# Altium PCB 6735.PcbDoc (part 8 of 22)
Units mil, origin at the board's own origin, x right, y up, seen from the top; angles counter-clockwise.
Board outline 2641.73 x 5165.35 mil, 6 copper layers (Top, Inner Layer 2, Inner Layer 3, Inner Layer 4, Inner Layer 5, Bottom), stack 35.7 mil thick; 1011 components, 790 nets, 4118 pads, 9325 vias.
Unrouted connection lines stored in the file: 4610.
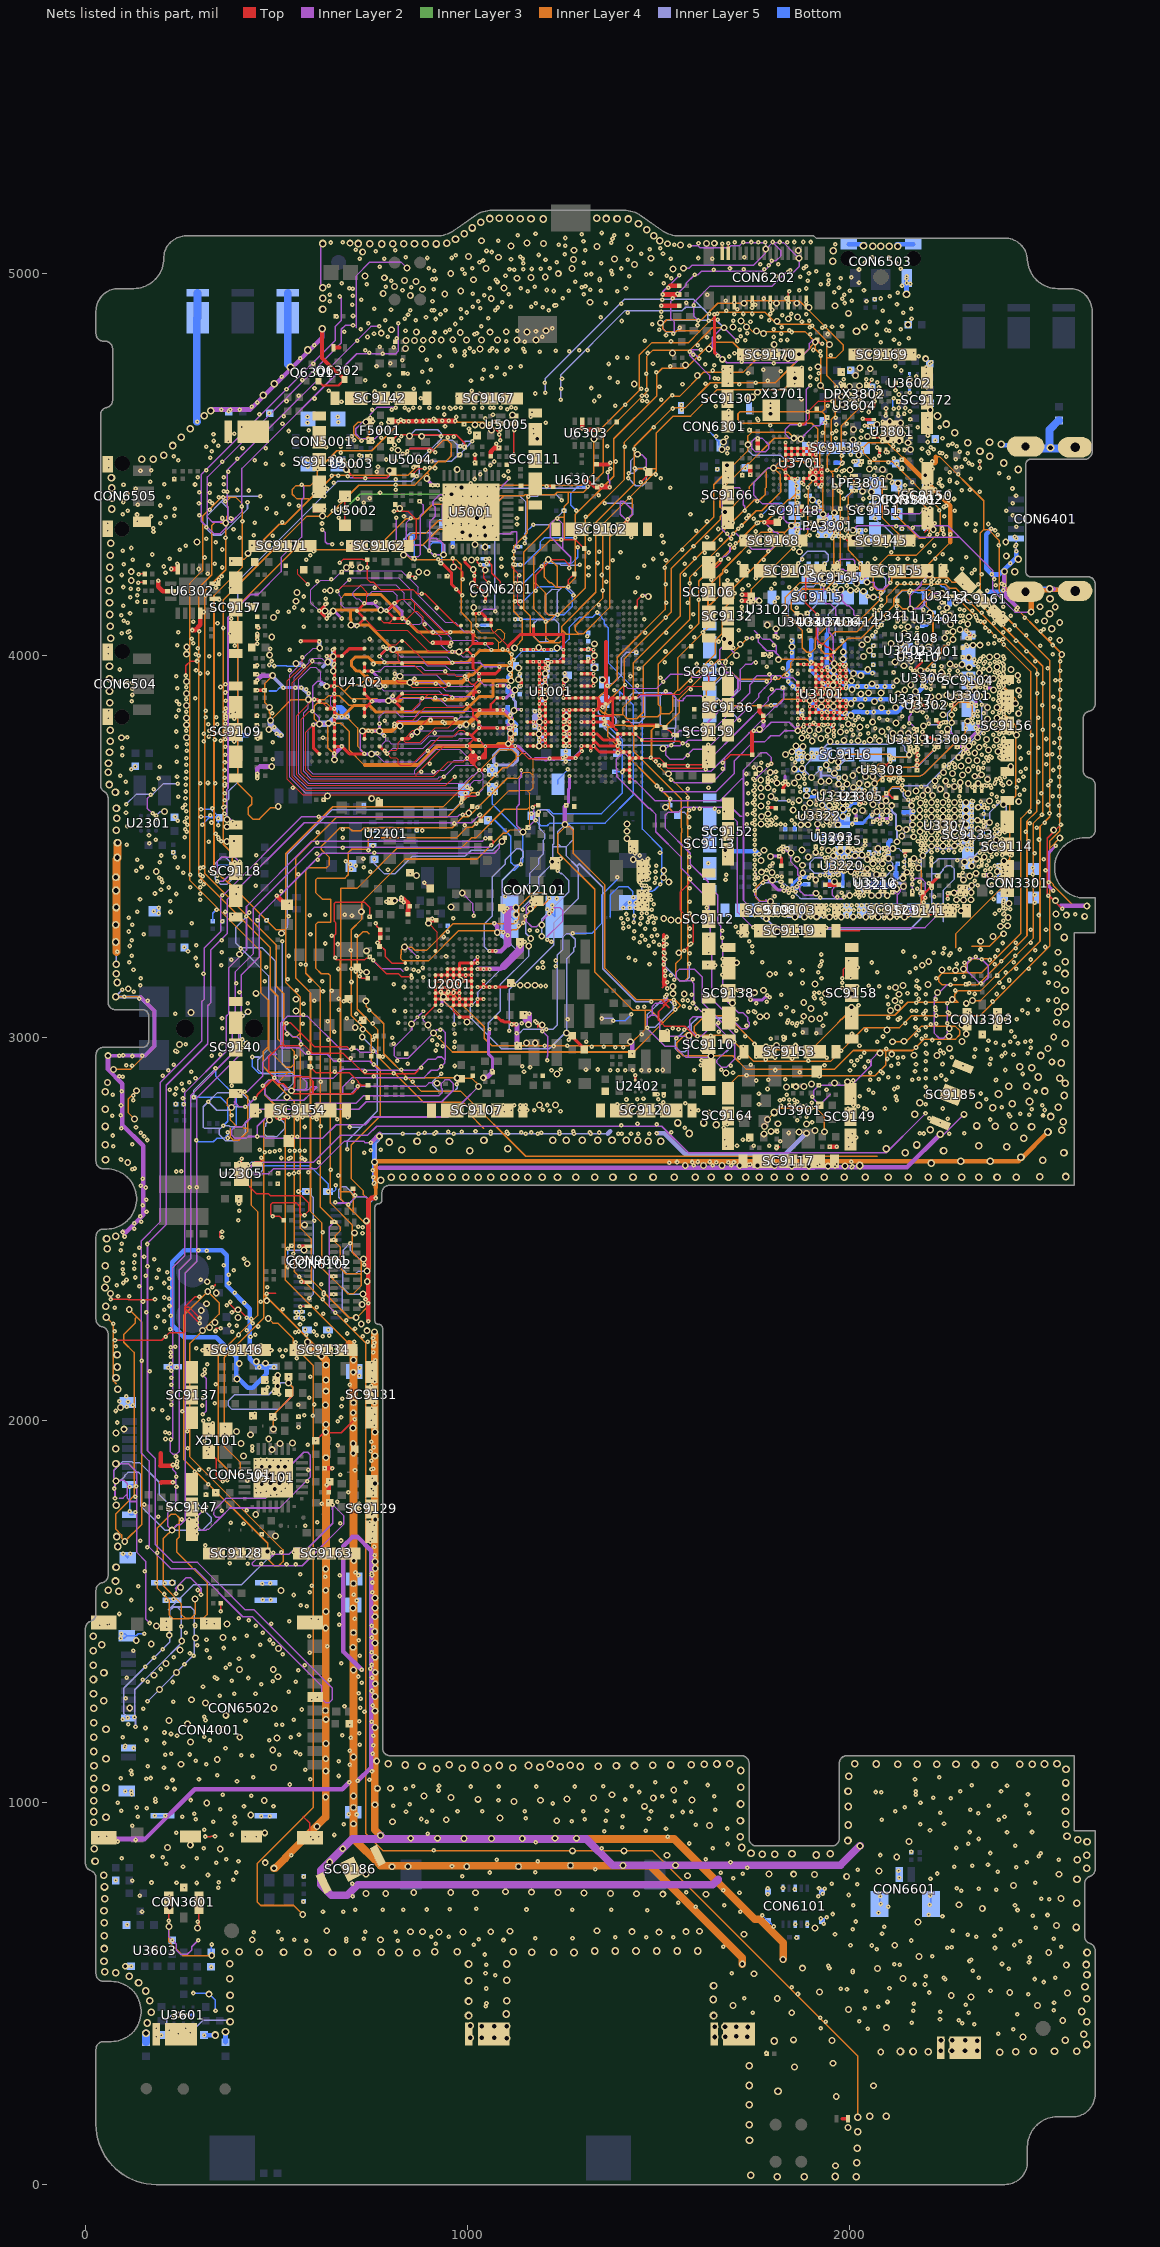
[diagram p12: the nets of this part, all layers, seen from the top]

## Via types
v1: diameter 12, hole 4, Top to Inner Layer 2, 3329 vias
v2: diameter 12, hole 4, Inner Layer 5 to Bottom, 3071 vias
v3: diameter 18, hole 10, Inner Layer 2 to Inner Layer 5, 1928 vias
v4: diameter 10, hole 4, Top to Inner Layer 2, 525 vias
v5: diameter 20, hole 12, Top to Bottom, 472 vias

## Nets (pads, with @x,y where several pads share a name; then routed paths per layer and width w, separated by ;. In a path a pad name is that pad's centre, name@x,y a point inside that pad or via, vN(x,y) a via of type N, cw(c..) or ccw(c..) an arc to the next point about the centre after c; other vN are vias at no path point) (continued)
D_GND: (continued)
  Inner Layer 2 w3: v3(583.08,3885.11) 583.08,3863.03 570.58,3850.53 570.58,3697.87 589.84,3678.61 921.29,3678.61 925.92,3683.23 v1(937.75,3683.23) 943.07,3688.56 944.07,3688.56 968.34,3712.83 1017.91,3712.83 v4(1029.98,3700.77) ; v1(593.83,3986.11) 598.33,3981.61 v3@629.08,3981.61 ; v1(596.08,3819.11) 582.58,3805.61 582.58,3702.84 594.82,3690.61 862.05,3690.61 ; v1(611.81,4117.11) 590,4138.92 590,4172.54 614.95,4197.49 647.13,4197.49 v1@671.92,4222.28 ; v3(613.08,4020.11) 595.34,4020.11 v1@571.39,3996.15 ; 616.08,3933.11 616.08,3956.11 602.58,3969.61 589.33,3969.61 558.58,3938.86 558.58,3691.36 583.33,3666.61 991.33,3666.61 1012.33,3687.61 1016.82,3687.61 v4(1029.98,3700.77) ; v1(651.18,3743.1) v3(651.27,3727.69) ; v1(651.18,3861.21) 642.34,3870.05 642.34,3891.74 v1(651.18,3900.58) ; v1(670.07,4219.89) v1@671.92,4222.28 ; v3(748.08,3743.11) 759.08,3743.11 780.08,3722.11 866.08,3722.11 910.85,3766.88 995.36,3766.88 v4(998.48,3763.76) ; v1(749.61,3959.63) 769.61,3959.63 782.58,3972.61 877.33,3972.61 887.83,3962.11 935.83,3962.11 947.83,3950.11 989.83,3950.11 998.08,3941.86 998.08,3937.38 v4(998.48,3936.99) ; v3(769.08,3803.11) 785.08,3787.11 785.08,3777.11 ; v3(769.08,3920.11) 769.29,3919.89 781.08,3908.11 923.83,3908.11 935.83,3896.11 959.83,3896.11 959.83,3890.49 v1(959.95,3890.49) ; v1(769.29,3821.84) 769.29,3840.11 783.08,3853.89 811.54,3853.89 823.33,3842.11 862.33,3842.11 874.83,3854.61 1029.58,3854.61 1031.08,3856.11 v4@1033.08,3856.11 ; v1(769.29,3999) 783.69,3984.61 883.33,3984.61 893.83,3974.11 941.83,3974.11 953.83,3962.11 1000.87,3962.11 1000.99,3962.23 1020.48,3962.23 v4(1029.98,3952.73) ; v1@788.59,3743.1 776.08,3755.61 776.08,3768.11 785.08,3777.11 ; v1@791.99,3746.11 803.99,3758.11 884.08,3758.11 905.08,3779.11 974.83,3779.11 979.33,3783.61 1025.87,3783.61 v4(1029.98,3779.51) ; v3@793.58,3882.11 800.58,3889.11 v1@876.08,3889.11 ; v3(805.08,4016.11) 824.58,3996.61 944.83,3996.61 960.02,3981.8 v1@960.21,3981.61 ; v1(808.66,4136.8) 816.15,4144.29 816.15,4156.32 804.2,4168.28 750.3,4168.28 736.06,4154.04 736.06,4142.93 v1(729.92,4136.8) ; v1@808.81,3880.75 835.45,3854.11 856.58,3854.11 876.08,3873.61 v1@876.08,3889.11 ; v1@808.92,3939.95 v3@819.08,3950.11 ; v1@809.51,3822.68 815.43,3828.61 866.83,3828.61 879.58,3841.36 960.58,3841.36 968.6,3833.34 v1(968.71,3833.45) 968.83,3833.11 974.83,3833.11 982.33,3840.61 1016.12,3840.61 1029.98,3826.74 ; v3(823.08,3946.11) v3@819.08,3950.11 ; v1(828.35,4097.43) 844.05,4081.72 874.93,4081.72 881.08,4087.88 881.08,4096.57 ; v3(849.08,3930.11) 849.58,3930.61 919.58,3930.61 942.08,3908.11 1027.36,3908.11 v4(1029.98,3905.48) ; v3(867.08,3800.11) 870.08,3803.11 962.83,3803.11 973.46,3813.73 989.71,3813.73 v3(996.08,3820.11) ; v3(977.08,4010.11) v3@977.08,4006.11 ; v4(998.48,3873.99) 992.98,3868.49 945.45,3868.49 924.83,3889.11 v1@876.08,3889.11 ; v4@1001.65,3729.09 1004.13,3726.61 989.41,3726.61 ; v1@1008.58,3653.83 1008.58,3665.11 1008.21,3665.48 ; v4(1014.23,3999.98) 1010.86,3996.61 986.58,3996.61 v3@977.08,4006.11 ; v4(1014.23,4062.97) 990.97,4062.96 966.89,4087.05 941.52,4087.05 870.15,4158.41 870.15,4178.71 826.59,4222.28 v1@671.92,4222.28 ; v4(1029.98,3811) 1029.58,3810.6 1014.59,3795.61 973.33,3795.61 968.83,3791.11 899.08,3791.11 878.08,3770.11 800.08,3770.11 793.08,3777.11 785.08,3777.11 ; v4(1029.98,3779.51) 1029.98,3779.21 v4(1046.08,3763.11) ; 1035.08,3855.11 v4@1034.08,3856.11 ; v4@1061.59,4015.61 v4(1045.72,4031.47) 1045.73,4032.23 1029.96,4032.23 1022.08,4040.11 962.83,4040.11 v1(956.83,4034.11) 956.83,4046.28 852.15,4150.96 852.15,4171.23 819.11,4204.28 694.25,4204.28 v1(658.33,4168.36) 663.58,4168.36 663.58,4157.86 668.08,4153.36 670.95,4153.36 669.1,4151.5 669.1,4133.79 677,4125.88 719,4125.88 v1(729.92,4136.8) ; v4@1077.22,3921.24 1074.12,3924.33 1042.01,3924.33 1036.06,3930.28 1036.06,3930.9 v4(1029.98,3936.99) 1013.1,3920.11 947.83,3920.11 917.83,3950.11 v3@819.08,3950.11 ; 1145.29,3750.49 1148.88,3750.49 1168.86,3730.51 1177.33,3730.51 ; v4(1392.18,3763.76) 1392.18,3778.6 1412.4,3798.83 1429.44,3798.83 1430.44,3797.83 1435.56,3797.83 1448.87,3784.52 1533.75,3784.52 v1@1539.31,3790.09 ; v4(1411.9,3923.47) 1411.9,3921.5 1418.31,3915.09 1494.31,3915.09 v1(1511.31,3932.09) ; v1(1750.72,3384.72) 1750.72,3372.95 1765.58,3358.09 1778.69,3358.09 1779.76,3357.02 v3(1791.99,3357.02) ; v1@571.39,3996.15 573.51,3994.03 570.96,3991.48 554.96,3975.48 554.31,3974.83 554.31,3969.6 534.58,3949.87 534.58,3681.42 574.91,3641.09 988.31,3641.09 995.31,3634.09 1022.41,3634.09 1040.58,3652.26 1040.58,3679.36 ; v1@571.39,3996.15 v1(566.95,3995.49) 566.73,3991.5 568.84,3993.6 v1@571.39,3996.15 ; v3@629.08,3981.61 631.5,3982.33 631.82,3982.43 v3(634.08,3983.11) 635.58,3981.61 v3@629.08,3981.61 ; v3@629.08,3981.61 629.08,3982.85 618.32,3993.61 590.72,3993.61 588.52,3991.41 585.41,3988.29 585.41,3982.66 546.58,3943.83 546.58,3686.39 578.36,3654.61 997.33,3654.61 1008.21,3665.48 ; v1(729.92,4136.8) 727.07,4136.8 714.55,4149.32 708.92,4149.32 699.53,4158.71 699.53,4161.9 700.97,4163.34 700.97,4166.16 721.08,4186.28 811.65,4186.28 834.15,4163.78 834.15,4143.5 881.08,4096.57 ; 862.05,3690.61 862.05,3700.59 916.13,3754.67 978.78,3754.67 998.48,3734.97 v4(998.48,3732.26) 995.06,3732.26 989.41,3726.61 ; 862.05,3690.61 912,3690.61 921.98,3700.59 938.82,3700.59 964.84,3726.61 989.41,3726.61 ; 881.08,4096.57 891.48,4086.17 912.8,4064.85 931.23,4046.42 931.23,4027.89 950.51,4008.61 974.58,4008.61 v3@977.08,4006.11 ; 1008.21,3665.48 1016.83,3674.11 1023.89,3674.11 ; 1023.89,3674.11 1035.33,3674.11 ; 1023.89,3674.11 1024.48,3673.52 1034.74,3673.52 1035.33,3674.11 ; v4(1029.98,3700.77) 1040.58,3690.16 1040.58,3679.36 ; v4@1033.08,3856.11 v4(1031.08,3858.11) 1032.08,3858.11 v4@1034.08,3856.11 ; v4@1033.08,3856.11 v4@1034.08,3856.11 ; 1035.33,3674.11 1040.58,3679.36
  Inner Layer 2 w4: v3(65.31,2330.92) 65.59,2331.2 65.95,2330.83 v1(65.95,2315.83) ; v1(77.31,1796.09) 77.31,1838.09 v3(80.31,1841.09) ; 88.31,1796.09 98.53,1796.09 109.31,1806.87 ; v1(168.31,1469.09) 157.31,1480.09 157.31,1630.98 134.51,1653.78 134.51,1787.09 ; v1(171.28,3635.71) 161.31,3625.74 161.31,3601.09 175.07,3587.33 v1(176.03,3587.33) ; v1(218.31,690.09) 218.31,678.09 217.31,677.09 217.31,675.09 v3(218.31,675.09) 218.31,648.26 237.31,629.26 237.31,613.82 249.03,602.11 265.62,602.11 265.78,602.26 266.41,602.26 278.12,613.98 278.12,621.91 v1(295.3,639.09) ; v1(229.06,1882.65) 228.31,1879.43 228.31,1871.09 236.51,1862.89 236.51,1851.77 236.51,1778.75 215.31,1757.55 215.31,1723.09 v3(226.31,1712.09) 240.31,1726.09 248.8,1726.09 261.31,1738.6 261.31,2384.98 291.31,2414.98 291.31,2842.72 401.31,2952.72 401.31,3037.29 407.31,3043.29 407.31,3164.54 455.31,3212.54 455.31,3321.35 456.31,3322.35 456.31,3322.44 497.02,3363.15 497.12,3363.15 501.75,3367.78 504.12,3367.78 619.42,3483.09 1069.36,3483.09 1082.31,3496.04 1082.31,3504.83 1090.35,3512.87 v3(1089.69,3513.53) v3@1090.39,3516.8 ; 235.31,1560.09 236.95,1561.72 ; v1(236.95,1545.49) 236.95,1561.72 ; v1(302.31,1543.09) 302.31,1560.06 275.29,1587.09 262.31,1587.09 242.85,1567.62 236.95,1561.72 ; v1(307.31,1763.09) 295.31,1751.09 295.31,1719.12 302.34,1712.09 315.1,1712.09 317.1,1714.09 322.11,1714.09 354.11,1746.09 ; v1(307.31,2015.09) 316.31,2024.09 316.31,2109.09 v1(307.31,2118.09) ; v1(344.27,3424.72) 344.27,3461.36 355.77,3472.87 391.5,3472.87 v1(403.36,3461) ; v1(344.95,3409.83) 360.53,3409.83 390.31,3439.62 v1(390.31,3460.09) ; v1(354.76,3514.14) 369.83,3514.14 v3(369.83,3513.77) ; v1@372.95,4486.49 v1@370.98,4484.51 ; v3(381.73,2818.12) 391.17,2827.55 394.31,2827.55 ; 389.31,2832.55 392.18,2829.68 ; v1(394.5,3556.6) 374.63,3576.47 369.31,3581.79 369.31,3649.04 372.95,3652.68 372.95,3801.78 372.95,3903.37 372.95,4100.69 432.36,4160.09 452,4160.09 511.95,4220.04 511.95,4256.92 565.31,4310.28 565.31,4407.91 571.07,4413.67 571.07,4442.07 v1(565.41,4447.73) ; v1(404.79,2855.36) 392.18,2842.76 392.18,2829.68 ; v1@421.18,2858.09 464.31,2901.22 464.31,2936.63 484.77,2957.09 500.99,2957.09 ; v1(443.11,2842.42) 420.79,2820.09 401.78,2820.09 394.31,2827.55 ; v1(525.95,3038.57) 522.31,3038.57 522.31,3022.26 531.95,3012.62 540.74,3003.83 541.48,3003.09 553.28,3003.09 563.95,2992.42 v1(563.95,2983.83) ; v3(612.08,3821.11) v3@612.08,3822.11 ; v1(619.95,4329.83) 627.6,4322.18 627.6,4298.38 632.89,4293.09 644.69,4293.09 v1(645.95,4291.83) ; v5(620.65,4963.09) 615.65,4968.09 615.65,5072.71 v5(621.25,5078.31) ; v1(621.69,3623.09) 621.97,3622.81 632.6,3633.44 v3(632.88,3633.16) ; v3(636.08,3823.11) 636.08,3822.11 v3@612.08,3822.11 ; v1(650.95,2518.49) 637.3,2504.84 637.3,2297.1 v1(653.31,2281.09) ; v1(651.18,3920.26) 631.5,3920.26 618.65,3933.11 616.08,3933.11 607.08,3933.11 594.08,3920.11 594.08,3885.37 594.08,3855.36 612.08,3837.36 v3@612.08,3822.11 ; v1(653.3,2570.09) 655.3,2568.09 691.1,2568.09 707.1,2584.09 734.31,2584.09 739.31,2579.09 759.31,2579.09 v1(759.31,2581.09) ; v1(661.95,4382.49) v3(677.48,4382.29) ; v1(664.95,4939.83) 668.95,4935.83 668.95,4876.73 652.95,4860.73 652.95,4824.3 302.95,4474.3 302.95,4351.83 335.95,4318.83 352.31,4318.83 369.31,4335.83 v3@369.31,4345.09 ; v1(685.74,4469.48) 688.93,4469.48 693.31,4465.09 789.31,4465.09 796.39,4472.17 796.39,4479.34 v3(795.34,4484.55) ; v1(699.95,4864.83) 680.01,4864.83 669.31,4854.14 669.31,4818.01 318.95,4467.65 318.95,4404.38 318.95,4362.83 331.95,4349.83 369.31,4349.83 v3@369.31,4345.09 ; 708.95,4857.65 708.95,4994.69 744.09,5029.83 825.57,5029.83 v3(841.31,5014.09) ; v3(725.08,3803.11) 718.95,3796.98 718.95,3754.07 v1(729.92,3743.1) ; v3(733.91,4611.3) 724.91,4611.3 716.69,4603.09 707.31,4593.72 707.31,4580.46 719.68,4568.09 758.31,4568.09 773.95,4583.73 v1(773.95,4606.49) ; v1(743.79,3211.76) 774.46,3181.09 824.31,3181.09 831.31,3174.09 ; v1(745.11,4622.95) 745.11,4631.09 760.31,4646.83 763.57,4650.09 807.69,4650.09 810.71,4647.07 v1(812.33,4648.69) ; v1(746.95,2725.83) 732.08,2725.83 728.82,2729.09 676.71,2729.09 604.71,2657.09 491.06,2657.09 479.06,2645.09 442.33,2645.09 433.31,2654.11 433.31,2666.07 442.33,2675.09 597.03,2675.09 667.03,2745.09 737.88,2745.09 761.88,2769.09 1508.05,2769.09 1577.58,2699.56 2095.02,2699.56 2183.55,2788.09 v1(2197.95,2802.49) ; v1(768.95,4861.49) 746.81,4861.49 370.41,4485.08 v1@370.98,4484.51 ; v3@769.29,3919.89 v3@769.29,3921.11 ; v1(778.31,2951.09) 769.04,2951.09 757.04,2963.09 717.99,2963.09 710.99,2970.09 v1(695.95,2970.09) 667.11,2970.09 581.11,3056.09 528,3056.09 511.31,3039.4 511.31,2975.41 515.31,2971.41 518.73,2974.83 557.9,2974.83 575.77,2956.96 632.43,2956.96 650.43,2938.96 694.04,2938.96 694.17,2939.09 743.97,2939.09 766.95,2916.11 766.95,2915.09 ; v1@788.59,3743.1 v1(788.98,3743.1) ; v3@803.08,4018.11 803.08,4018.69 v3(805.08,4016.11) ; v1(808.66,3821.84) v1@809.51,3822.68 ; v1(808.66,3939.95) v1@808.92,3939.95 ; v3(809.31,3359.09) 809.31,3359.59 826.31,3359.59 v1(826.31,3360.09) ; v1(812.71,4360.88) 812.71,4294.49 838.22,4268.99 848.72,4258.49 869.95,4258.49 876.31,4264.85 876.31,4289.85 ; v1(817.95,4869.49) 817.95,4796.49 811.55,4790.09 709.53,4790.09 409.31,4489.87 409.31,4377.09 381.31,4349.09 375.52,4349.09 v3@374.15,4347.72 ; v3(834.79,3238.14) 834.79,3237.29 842.89,3237.29 868.41,3211.77 869.07,3211.11 v4@868.95,3210.99 ; v1(841.89,4535.07) 848.91,4542.09 905.31,4542.09 v1(915.31,4532.09) ; v1(850.95,4359.49) 838.95,4347.49 838.95,4304.96 854.43,4289.49 875.95,4289.49 876.31,4289.85 ; v1(873.95,4403.98) 883.31,4394.61 883.31,4374.55 876.31,4367.55 876.31,4289.85 ; v3(879.64,4574.27) 882.79,4577.42 926.53,4577.42 v1(930.27,4573.68) ; v4(884.09,3054.22) 884.08,3045.56 v3(896.26,3033.38) ; v4(884.09,3069.96) v4(868.34,3054.22) 869.1,3053.45 852.52,3036.87 v3(853.29,3036.1) 853.29,3020.94 807.31,2974.97 807.31,2954.12 814.34,2947.09 844.31,2947.09 v3(910.31,3013.09) 918.09,3020.87 934.53,3020.87 940.98,3014.42 940.98,2942.73 940.31,2942.06 ; v3(919.7,2881.33) v3@924.31,2882.09 ; v1(939.3,4421.28) 926.54,4421.28 909.31,4404.06 909.31,4394.11 915.31,4388.11 915.31,4365.1 900.31,4350.1 900.31,4306.09 ; v3(957.29,4422.28) 957.29,4417.21 955.59,4417.21 932.95,4394.58 932.95,4348.49 966.95,4314.49 v1(966.95,4305.49) ; v1(959.83,3981.61) 960.21,3981.61 1033.17,3981.61 1044.29,3970.49 v4(1082.95,3970.49) ; v1(959.95,3890.49) 961.55,3892.09 1014.23,3892.09 v4(1014.23,3889.74) ; v3(985.95,3378.83) 1012.95,3351.83 1012.95,3333.24 1016.31,3329.88 v1(1016.31,3319.24) ; v1(987.42,3583.34) 978.21,3583.34 973.96,3579.09 565.79,3579.09 354.3,3367.6 354.3,3279.15 311.31,3236.16 311.31,3101.85 303.96,3094.49 303.96,2991.44 195.31,2882.8 195.31,2518.4 146.31,2469.4 146.31,1913.29 166.51,1893.09 166.51,1668.11 223.17,1611.45 285.84,1611.45 411.65,1485.65 436.72,1485.65 617.63,1304.73 617.63,1271.8 628.34,1261.09 638.28,1261.09 645.31,1268.12 645.31,1299.68 441.11,1503.88 417.22,1503.88 293.4,1627.71 229.54,1627.71 182.51,1674.74 182.51,1899.9 162.31,1920.1 162.31,2462.58 211.31,2511.58 211.31,2876.11 320.11,2984.91 320.11,3084.39 327.31,3091.6 327.31,3229.49 370.63,3272.81 370.63,3361.3 572.42,3563.09 1010.89,3563.09 1025.45,3577.65 1026.34,3577.65 v1(1032.3,3583.61) ; v4(992.95,3180.49) 1003.27,3180.49 1016.14,3193.36 1016.14,3202.02 v4(1025.82,3211.7) ; v3(997.95,3041.83) 997.95,3042.1 v4(1010.07,3054.22) ; v4(998.48,3732.26) 1001.65,3729.09 1026.8,3729.09 v4(1029.98,3732.26) ; v3(1028.62,2872.67) v3@1028.6,2872.86 ; v4@1029.58,3810.6 v4(1029.98,3811) ; v4(1029.98,3700.77) v4(1045.72,3700.77) ; v4(1029.98,4110.21) 1041.86,4122.09 1075.31,4122.09 ; v1(1046.62,3522.84) 1038.87,3515.09 592.3,3515.09 421.31,3344.1 421.31,3229.94 375.31,3183.94 375.31,3063.71 368.31,3056.71 368.31,2964.98 259.31,2855.98 259.31,2430.24 228.31,2399.24 228.31,2191.16 228.31,2128.99 228.31,2040.13 228.31,1950.52 221.31,1943.52 221.31,1918.12 228.34,1911.09 238.28,1911.09 245.31,1918.12 245.31,2392.52 275.31,2422.52 275.31,2849.35 384.31,2958.35 384.31,3046.66 391.31,3053.66 391.31,3172.54 439.31,3220.54 439.31,3339.47 598.93,3499.09 1054.98,3499.09 1060.97,3505.08 v1(1062.02,3504.03) ; v1(1106.95,4464.49) 1106.95,4460.09 1071.31,4424.45 1071.31,4327.87 1080.1,4319.09 1111.31,4319.09 1116.71,4324.49 1128.95,4324.49 1128.95,4281.49 v1(1120.95,4273.49) ; v4(1140.21,3700.77) 1140.21,3682.49 1134.95,3677.23 1134.95,3611.07 1128.95,3605.07 1128.95,3555.09 1139.95,3544.09 1150.69,3544.09 1173.3,3566.7 1173.3,3600.14 v1@1170.95,3602.49 ; v1(1166.95,3356.83) 1152.95,3342.83 1152.95,3305.62 1167.74,3290.83 1180.17,3290.83 1197.95,3308.62 1197.95,3310.28 v1@1213.16,3325.49 ; v1(1171.51,4593.7) 1171.31,4593.7 1171.31,4578.37 v3(1182,4567.68) ; v1(1194.95,3017.83) 1209.39,3003.39 1209.39,2952.85 1208.28,2951.74 v1(1208.28,2941.03) ; 1206.95,3263.83 1249.14,3306.02 1249.14,3333.61 1241.92,3340.83 1226.76,3340.83 v1(1220.95,3335.02) ; 1207.31,4437.09 v1(1207.31,4443.09) ; v4(1218.95,3984.23) 1234.51,3984.23 1239.25,3988.97 1245.7,3995.41 ; 1245.7,3995.42 1250.45,4000.17 v4@1250.45,4015.72 ; v1(1265.89,4229.49) 1265.89,4239.35 1269.89,4243.35 1269.89,4257.65 1247.45,4280.09 ; v1(1371.31,4441.23) 1371.31,4457.22 1367.31,4461.22 1367.31,4482.65 1373.41,4488.74 v1(1372.72,4489.43) ; v4@1423.68,3889.74 1446.75,3889.74 1452.1,3895.09 1504.63,3895.09 1511.63,3902.09 1531.27,3902.09 1551.53,3881.83 1563.95,3881.83 1563.95,3886.04 1572.74,3894.83 1610.64,3894.83 1617.88,3887.6 1625.13,3887.6 1629.23,3883.49 1638.71,3883.49 1641.11,3881.09 1662.72,3881.09 1667.5,3885.88 1685.62,3885.88 1694.41,3894.66 1694.41,3901.07 1696.21,3902.87 1696.21,3903.51 1707.31,3914.61 1707.31,3938.75 1690.17,3955.89 1677.74,3955.89 1674.77,3952.92 ; v3(1444.2,4526.99) 1444.2,4526.09 1455.2,4526.09 1467.43,4513.86 1467.43,4490.09 v1(1464.31,4489.09) ; v1(1457.52,4156.53) 1458.31,4159.09 1468.31,4159.09 v3(1472.66,4154.69) ; v1(1495.31,3659.09) 1502.16,3652.25 1502.16,3650.93 1504.51,3648.58 1509,3644.09 1649.71,3644.09 1697.65,3692.03 1697.65,3724.69 1748.14,3775.17 1761.15,3775.17 1761.21,3775.24 1777.67,3775.24 1793.06,3790.63 1816.1,3790.63 1829.07,3803.59 v3(1863.65,3803.59) 1841.49,3825.75 1794,3825.75 1769.76,3801.51 1767.74,3799.49 1738.51,3799.49 1736.48,3797.45 ; v1(1510.31,4945.09) 1510.31,4952.09 v1(1553.31,4995.09) ; v1(1511.31,3932.09) 1530.31,3951.09 1581.58,3951.09 1589.51,3943.16 1599.34,3943.16 1599.97,3943.79 1608.43,3943.79 1616.23,3951.59 1673.44,3951.59 1674.77,3952.92 ; v1(1521.31,3113.09) 1521.31,3101.71 1519.32,3099.71 1510.69,3091.09 1491.71,3091.09 1483.31,3082.69 1483.31,3059.09 ; v3(1525.31,3691.09) 1532.35,3698.13 1637.15,3698.13 1672.29,3733.27 ; v1(1532.06,3675.97) 1539.94,3668.09 1639.67,3668.09 1672.29,3700.71 1672.29,3733.27 ; v1(1537.95,4841.83) 1540.95,4841.83 1540.95,4872.8 1530.95,4882.8 1530.95,4926.83 1537.95,4933.83 v1(1536.95,4934.83) 1538.45,4935.33 1549.45,4946.33 v1(1548.95,4946.83) 1571.45,4969.33 1571.45,4974.33 v1(1593.95,4996.83) 1602.73,4996.83 1611.18,5005.29 1774.72,5005.29 1787.95,5018.52 v1(1787.95,5021.83) 1799.39,5033.27 1806.63,5033.27 1819.45,5046.08 1819.45,5059.33 1797.95,5080.83 v1(1798.44,5082.36) ; v1(1538.31,3793.09) 1539.31,3790.09 1540.45,3790.09 1553.45,3803.09 1605.49,3803.09 1618.77,3816.37 1640.01,3837.61 1640.01,3837.68 1654.31,3851.98 1654.31,3852.46 1713.74,3911.9 1713.74,3964.07 1726.85,3977.17 1741.87,3977.17 1749.29,3984.59 1756.65,3984.59 1754.15,3982.09 v1(1754.01,3982.23) ; v3(1564.95,5013.83) 1578.95,5013.83 1586.95,5021.83 1747.95,5021.83 1778.95,5052.83 1778.95,5063.83 v3@1779.45,5063.83 ; v1(1580.31,5073.09) 1601.73,5073.09 1606.98,5067.83 1684.14,5067.83 1689.14,5072.83 1710.85,5072.83 1718.85,5080.83 1720.91,5080.83 v1(1720.91,5082.12) 1720.95,5080.83 1741.89,5080.83 v1(1741.89,5082.29) 1741.95,5080.83 v1@1759.94,5080.83 ; v1@1591.24,3151.44 v1(1589.27,3153.41) ; v1(1603.31,4877.09) 1591.31,4889.09 1591.31,4924.06 1634.34,4967.09 1796.71,4967.09 1829.71,5000.09 1849.29,5000.09 1866.95,5017.75 v3(1866.95,5039.83) 1855.06,5051.72 1855.06,5051.91 1826.14,5080.83 1817.05,5080.83 v1(1817.05,5082.31) 1816.95,5080.83 1798.44,5080.83 v1(1798.44,5082.36) ; v1(1605.95,4777.49) 1599.59,4783.85 1599.59,4784.25 1588.85,4794.99 v1(1580.85,4794.99) ; v1(1610.31,4800.09) 1594.69,4800.09 1594.13,4800.65 1586.5,4800.65 v1(1580.85,4794.99) ; v1(1624.31,3726.13) v1(1624.31,3726.13) 1630.32,3726.09 1712.01,3807.79 1712.01,3807.86 1785.95,3881.8 1785.95,3889.16 1785.95,3890.59 1800.62,3905.25 1800.62,3905.58 1807.65,3912.6 1817.59,3912.6 1817.75,3912.44 1824.77,3912.44 1826.65,3910.56 1826.65,3884.62 1820.17,3878.14 1809.29,3867.24 1805.33,3867.24 1736.01,3797.92 1736.48,3797.45 ; v1(1626.79,3311.09) v1@1630.79,3311.09 ; v1(1630.31,3264.09) v1@1634.95,3264.09 ; 1632.95,4723.38 1632.95,4733.4 1580.85,4785.5 v1(1580.85,4794.99) ; v3(1636.31,2953.09) 1632.31,2949.09 1577.31,2949.09 ; v1(1645.99,3599.84) 1648.72,3599.84 1651.31,3602.43 1651.31,3603.09 ; v1(1662.31,4251.39) 1670.67,4259.74 1674.49,4259.74 1686.31,4271.57 v1(1686.31,4290.09) ; v1(1666.59,3238.74) 1666.59,3259.49 1665.12,3260.96 1662.74,3263.34 1662.74,3292.1 1654.79,3300.05 1654.79,3373.09 1629.44,3398.45 1629.44,3408.5 1582.63,3455.3 1582.63,3482.96 1516.32,3549.27 1516.32,3550.69 1516.75,3551.12 1516.75,3569.12 1516.68,3569.19 1516.68,3581.61 1516.75,3581.68 1516.75,3582.44 1524.4,3590.09 1525.16,3590.09 1525.48,3590.41 1537.89,3590.41 1538.21,3590.09 1550.52,3590.09 1564.52,3604.09 1645.99,3604.09 1651.31,3604.09 ; 1667.41,3245.35 1667.41,3238.74 1667.41,3119.71 1669.44,3117.68 1669.44,3105.35 v3@1688.4,3086.39 ; v1(1690.08,4306.11) 1666.31,4329.88 1666.31,4425.79 1679.61,4439.09 1711.53,4439.09 1721.31,4429.3 1721.31,4394.76 1724.98,4391.09 v1(1724.98,4378.74) ; v3(1692.95,3091.6) 1692.95,3091.4 1693.18,3091.17 v3@1688.4,3086.39 ; 1703.31,4320.09 1703.31,4318.87 1743.1,4279.09 1794.53,4279.09 1817.31,4301.87 1817.31,4314.3 1808.53,4323.09 1802.31,4323.09 v1(1776.31,4349.09) ; v3(1703.65,4000.59) 1703.65,4001.08 1680.24,4024.49 1668.25,4024.49 1659.08,4015.32 1659.08,3983.39 v1(1674.77,3967.7) 1674.77,3952.92 ; v1(1705.31,4823.09) v3(1670.31,4858.09) 1665.31,4858.09 1639.31,4832.09 1639.31,4804.87 1677.66,4766.52 1856.97,4766.52 1864.93,4774.49 ; 1717.65,3580.17 1713.19,3580.17 1673.27,3620.09 1659.75,3620.09 ; v1@1725.65,4049.59 v1(1729.65,4045.59) 1729.65,4045.73 1745.04,4045.73 v1(1745.04,4045.88) ; 1737.93,3923.27 1737.93,3902.14 1678.31,3842.52 1678.31,3842.04 1664.01,3827.74 1664.01,3827.67 1615.43,3779.09 1577.33,3779.09 1570.31,3772.08 1562.31,3772.08 v1(1562.31,3771.09) 1555.84,3764.62 1526.21,3764.62 1518.77,3757.18 1518.77,3739.63 1529.77,3728.64 1562.5,3728.64 1588.69,3754.82 1625.11,3754.82 1688.01,3817.73 1688.01,3817.8 1702.31,3832.1 1702.31,3832.58 1761.95,3892.22 1761.95,3899.1 1761.95,3900.52 1776.62,3915.19 1776.62,3915.52 1793.43,3932.33 1793.43,3933.35 1793.76,3933.68 1793.76,3942.95 1791.07,3945.63 1791.07,3947.59 ; 1737.94,3923.28 1737.94,3923.52 1747.85,3933.43 1747.85,3938.25 1757.19,3947.59 1791.07,3947.59 ; v1(1738.65,3342.59) 1721.65,3359.59 1721.65,3678.38 ; 1749.65,4065.59 1771.65,4043.59 1790.34,4043.59 1807.65,4026.28 1807.65,4006.59 ; v1(1750.65,3414.59) 1753.65,3412.83 1753.65,3433.59 ; v1(1750.65,3674.59) 1774.11,3698.04 1775.11,3698.04 v1(1794.65,3717.59) 1794.65,3733.59 1782.65,3745.59 1766.65,3745.59 ; v1(1760.65,4050.59) 1760.65,4034.9 1782.72,4012.83 1801.41,4012.83 1807.65,4006.59 ; 1767.96,3745.35 1766.31,3745.35 1721.65,3700.7 1721.65,3678.38 ; 1780.02,3361.97 1780.65,3361.35 1780.65,3358.59 ; v3(1800.31,4491.09) 1786.1,4491.09 1748.31,4453.3 1748.31,4420.12 1760.83,4407.61 1771.35,4397.09 1784.8,4397.09 1785.8,4398.09 1812.29,4398.09 1826.31,4384.06 1826.31,4357.87 1836.1,4348.09 1839.31,4348.09 v3(1847.31,4340.09) 1855.91,4331.49 1910.87,4331.49 v3@1910.87,4336.09 ; v3(1813.65,3989.59) 1813.65,4000.59 1807.65,4006.59 ; v1(1837.65,3391.59) 1851.35,3391.59 1866.65,3406.89 1866.65,3421.64 1865.65,3422.64 1865.65,3423.6 1864.65,3424.6 1864.65,3425.5 1863.65,3426.5 1863.65,3442.39 1845.65,3460.39 v3(1845.65,3483.59) ; v3(1853.31,4569.09) 1842.31,4569.09 1830.31,4581.09 1830.31,4591.06 1843.34,4604.09 v1(1868.31,4604.09) 1884.31,4604.09 1886.31,4606.09 1886.31,4697.09 v1(1896.31,4707.09) ; v4(1863.66,3914.34) 1863.66,3921.51 1860.53,3924.64 1860.53,3933.03 1851.72,3941.83 1823.73,3941.83 1817.97,3947.59 1791.07,3947.59 ; 1865.95,4773.46 1864.93,4774.49 ; v3(1871.31,4567.09) 1882.2,4577.98 1882.2,4578.77 1904.52,4601.09 1920.53,4601.09 1934.49,4615.04 1934.49,4617.26 v1(1941.31,4624.09) ; v1(1875.42,4368.16) 1884.35,4377.09 1919.87,4377.09 v3@1928.09,4368.87 ; v3(1876.65,3431.59) 1868.65,3423.59 1868.65,3385.31 1880.37,3373.59 1903.65,3373.59 1908.65,3378.59 v3(1911.65,3378.59) ; v4(1879.41,3977.33) v4(1895.16,3977.33) ; v3(1906.31,4332.09) v3@1910.87,4336.09 ; v3(1909.3,4821.09) 1903.81,4826.58 1894.3,4817.07 1894.3,4803.86 1864.93,4774.49 ; v1(1914.67,4107.68) 1915.62,4107.68 1944.62,4078.68 1944.62,4062.5 1956.68,4050.44 1956.68,3986.9 1944.37,3974.59 1935.57,3974.59 1926.65,3965.68 v4(1926.65,3961.58) ; v3(1916.48,4085.83) 1916.48,4029.31 v1(1921.36,4024.43) ; v3@1928.09,4368.86 v3(1929.31,4370.09) ; v1(1931.65,4186.09) 1931.65,4168.95 1929.15,4166.45 1929.15,4158.3 1928.56,4157.71 1928.56,4145.29 1937.35,4136.5 1937.53,4136.5 1937.63,4136.4 1948.14,4136.4 1956.04,4128.5 1956.54,4128.5 1957.04,4128 1963.35,4121.69 1963.35,4105.71 1965.49,4103.56 1965.49,4086.89 v3(1970.49,4086.89) ; 1943.31,4373.09 1943.31,4368.53 v3@1910.87,4336.09 ; 1949.06,2852.56 v1(1921.08,2824.58) 1904.95,2840.71 1904.95,2861.75 v1(1919.46,2876.26) 1993.71,2876.26 2004.57,2876.26 2055.24,2926.93 2055.24,2942.32 2078.43,2965.5 2079.21,2964.73 v3(2079.21,2960.09) ; 1959.31,4236.09 1975.37,4252.15 2008.54,4252.15 ; v3(1959.68,3409.09) 1959.68,3396.52 1957.24,3394.08 1957.24,3391.13 1954.22,3388.11 1954.22,3386.2 1953.65,3385.63 1953.65,3373.55 1963.61,3363.59 1978.52,3363.59 1987.86,3372.92 v3(1999.69,3372.92) ; v1(1969.65,4226.59) 1982.76,4226.59 1987.7,4221.65 2005.31,4221.65 2012.81,4229.15 2012.81,4247.87 2008.6,4252.09 ; v3(1976.65,4173.59) 1976.65,4161.91 1981.06,4157.5 1981.06,4142.29 1992.85,4130.5 1997.71,4130.5 2010.06,4118.15 2010.06,4108 v3(2020.06,4098) ; v3(2007.77,4328.17) 2019.43,4339.83 2152.13,4339.83 2182.31,4309.65 2194.7,4309.65 2194.88,4309.83 2208.95,4309.83 ; v1(2030.65,4202.59) 2040.25,4202.59 2053.81,4216.15 2094.03,4216.15 2102.81,4207.36 2102.81,4188.94 2094.03,4180.15 2092.51,4180.15 2086.43,4174.07 ; v3(2044.81,4192.15) 2063.87,4192.15 2063.87,4182.77 2072.65,4173.98 2073.87,4173.98 2086.3,4173.97 2086.4,4174.07 ; v1(2094.33,4396.09) 2094.33,4383.83 2107.33,4370.83 2182.04,4370.83 v1(2193.3,4382.09) ; v3(2140.64,3395.82) 2132.16,3387.33 2132.16,3382.94 2123.65,3374.43 2123.65,3346.31 2135.37,3334.59 2173.65,3334.59 v1(2193.65,3354.59) ; v3(2155.25,3740.69) 2156.66,3740.69 2156.66,3756.08 v1(2158.08,3756.08) ; v1(2160.65,3855.59) 2160.65,3846.59 2154.46,3840.4 2154.46,3827.06 v1(2175.34,3806.18) ; v1(2163.81,3381.58) 2163.81,3391.42 2162.65,3392.59 2162.65,3407.63 2172.61,3417.59 2186.69,3417.59 2197.6,3406.69 v1(2197.6,3366.48) ; v1(2164.95,4334.83) 2169.95,4339.83 2256.52,4339.83 2286.52,4309.83 ; v3(2208.31,4213.15) 2186.81,4191.65 2186.81,4185.86 2158.31,4157.36 2158.31,4126.25 v3@2155.68,4123.62 ; v1(2208.95,4316.83) 2208.95,4309.83 ; v1(2230.65,3322.59) 2196.62,3288.56 1895.47,3288.56 1894.94,3289.09 1801.76,3289.09 1801.44,3288.77 1746.19,3288.77 1705.65,3329.31 1705.65,3564.95 1667.51,3603.09 1651.31,3603.09 ; v3(2241.06,4163.5) 2240.81,4163.65 2220.81,4163.65 2180.78,4123.62 v3@2155.68,4123.62 ; 2246.04,2747.83 v3(2298.3,2800.09) ; v1(2254.84,3090.66) 2254.84,3009.16 2244.77,2999.09 2233.99,2999.09 2220.31,3012.77 2220.31,3058.64 2220.31,3105.3 2254.1,3139.09 v1(2263.31,3139.09) ; v3(2255.65,3808.59) 2269.51,3794.59 2269.51,3792.32 v1(2281.24,3780.59) ; v3(2474.31,4114.09) 2431.95,4114.09 2373.95,4172.09 2373.95,4222.72 2320.84,4275.83 2320.52,4275.83 2286.52,4309.83 ; v3(80.31,1841.09) 74.31,1847.09 74.31,1868.3 91.6,1885.59 112.3,1885.59 134.51,1863.38 134.51,1787.09 ; v3(80.31,1841.09) 80.31,1843.09 100.29,1843.09 109.31,1834.06 109.31,1806.87 ; 109.31,1806.87 109.31,1796.12 118.34,1787.09 134.51,1787.09 ; 354.11,1746.09 342.34,1746.09 335.31,1753.12 335.31,1763.06 368.34,1796.09 472.31,1796.09 535.81,1859.59 v1(533.31,1862.09) 533.31,1878.06 571.34,1916.09 581.29,1916.09 588.31,1909.06 588.31,1850.94 507.46,1770.09 378.11,1770.09 354.11,1746.09 ; v3@369.31,4345.09 v3(366.95,4346.83) 368.95,4344.83 v3@369.31,4345.09 ; v3@369.31,4345.09 v3@374.15,4347.72 ; v3@369.31,4345.09 370.42,4343.98 v3@374.15,4347.72 ; v1@370.98,4484.51 370.98,4390.88 372.31,4389.54 372.31,4349.56 v3@374.15,4347.72 ; 392.18,2829.68 394.31,2827.55 ; v1(449.31,2742.09) 449.31,2768.63 476.78,2796.09 597.57,2796.09 614.57,2813.09 714.88,2813.09 734.88,2833.09 932.15,2833.09 962.31,2863.25 962.31,2880.76 952.98,2890.09 940.56,2890.09 931.31,2880.84 931.31,2875.09 ; v1(449.31,2742.09) 466.31,2742.09 470.31,2738.09 621.12,2738.09 656.12,2773.09 731.92,2773.09 751.92,2793.09 948.72,2793.09 989.72,2834.09 989.83,2834.09 v3@1028.6,2872.86 ; v1(449.31,2742.09) 425.31,2742.09 420.31,2737.09 391.7,2737.09 382.31,2746.47 382.31,2757.71 391.7,2767.09 409.52,2767.09 423.39,2780.97 423.39,2781.78 454.45,2812.83 587.23,2812.83 603.49,2829.09 708,2829.09 728,2849.09 925.52,2849.09 932.95,2856.52 932.95,2867.08 931.31,2868.72 931.31,2875.09 ; v1(493.95,2895.83) 525.95,2863.83 572.33,2863.83 ; v1(493.95,2895.83) 498.95,2900.83 561.95,2900.83 568.69,2894.09 ; v1(493.95,2895.83) 487.75,2889.63 479.29,2889.63 469.31,2879.66 469.31,2853.32 485.8,2836.83 571.05,2836.83 587.31,2853.09 ; 568.69,2894.09 579.36,2883.42 579.36,2870.86 572.33,2863.83 ; 568.69,2894.09 647.76,2894.09 671.76,2918.09 730.13,2918.09 733.13,2915.09 766.95,2915.09 ; 572.33,2863.83 582.37,2863.83 591.37,2872.83 603.57,2872.83 605.31,2871.09 587.31,2853.09 ; 587.31,2853.09 673.31,2853.09 ; 673.31,2853.09 673.31,2871.27 698.13,2896.09 885.89,2896.09 904.89,2915.09 920.87,2915.09 940.31,2934.53 940.31,2942.06 ; 673.31,2853.09 693.97,2853.09 706.14,2865.26 706.14,2866.89 v1@712.34,2873.09 ; v1@712.34,2873.09 v1(712.51,2873.26) ; v1@712.34,2873.09 889.72,2873.09 898.72,2882.09 v3@924.31,2882.09 ; v1(712.51,2873.26) 712.31,2873.09 712.31,2875.09 712.48,2875.09 v1(712.51,2873.26) ; 766.95,2915.09 867.25,2915.09 896.25,2944.09 915.93,2944.09 921.93,2950.09 932.28,2950.09 940.31,2942.06 ; 900.31,4306.09 901.31,4307.09 917.69,4307.09 924.69,4300.09 929.4,4300.09 934.31,4295.18 934.31,4266.58 v3(936.78,4264.11) 909.29,4264.11 900.31,4273.09 900.31,4306.09 ; v3@924.31,2882.09 931.31,2875.09 ; v3@1028.6,2872.86 1028.57,2873.05 1028.64,2873.42 1029.31,2873.57 v3@1028.6,2872.86 ; v1@1233.41,4359.06 1230.97,4359.06 1215.95,4344.04 1215.95,4311.59 1247.45,4280.09 ; v1@1233.41,4359.06 v1(1233.93,4359.06) 1231.29,4361.17 v1@1233.41,4359.06 ; v1@1233.41,4359.06 1233.67,4358.8 1237.64,4354.83 1239.17,4354.83 1247.95,4346.04 1248.44,4345.55 1248.44,4281.08 1247.45,4280.09 ; 1483.31,3059.09 1479.04,3059.09 1469.31,3049.37 1469.31,3025.09 1516.31,2978.09 1542.29,2978.09 1571.29,2949.09 1577.31,2949.09 ; 1483.31,3059.09 1491.31,3059.09 1502.95,3047.45 1502.95,3019.92 1518.04,3004.83 1568.31,3004.83 1577.31,2995.83 1577.31,2949.09 ; v1(1589.27,3153.41) 1585.93,3150.07 1554,3150.07 1545.19,3158.87 1545.19,3171.28 1553.99,3180.08 1592.77,3180.08 1613.76,3159.09 1613.76,3092.82 1698.31,3008.27 1698.31,2944.35 1677.34,2923.38 1663.81,2923.38 1651.31,2935.88 1651.31,2940.58 1682.31,2971.58 1682.31,3001.33 1638.31,3045.33 ; v1(1589.27,3153.41) 1589.27,3144.21 1591.24,3142.24 1591.24,3093.08 v1(1589.43,3091.27) 1610.35,3070.35 1613.29,3070.35 1628.55,3055.09 ; 1628.55,3055.09 1589.28,3055.09 1581.31,3047.12 1581.31,3021.12 1598.34,3004.09 v1(1601.31,3004.09) 1611.53,3004.09 1638.31,3030.87 1638.31,3045.33 ; 1628.55,3055.09 1638.31,3045.33 ; v1@1630.79,3311.09 1630.79,3307.53 1630.67,3307.41 1630.67,3290.22 1634.95,3285.94 v1@1634.95,3264.09 ; v1@1630.79,3311.09 1630.79,3362.13 1579.38,3413.55 1579.38,3424.42 1558.31,3445.48 1558.31,3473.11 1492.32,3539.1 1492.32,3539.89 1492.31,3560.62 1492.68,3560.99 1492.68,3584.32 1476.34,3600.66 1473.71,3600.66 1389.63,3684.74 1389.63,3705.48 1388.31,3706.8 1388.31,3728.2 1404.21,3744.09 1411.66,3744.09 1423.31,3732.44 1423.31,3685.56 1436.79,3672.09 1438.85,3672.09 1490.85,3620.09 1659.75,3620.09 ; v1@1634.95,3264.09 1638.15,3260.89 1638.15,3209.56 1638.28,3209.43 1638.28,3102.43 1717.07,3023.64 1729.2,3023.64 1736.25,3030.69 1736.25,3040.61 1732.95,3043.91 1732.95,3053.3 1720.95,3065.3 1709.49,3065.3 v3@1688.4,3086.39 ; 1651.31,3603.09 1651.31,3604.09 ; 1651.31,3603.09 1650.65,3603.09 1651.31,3604.09 ; 1659.75,3620.09 1718.04,3678.38 1721.65,3678.38 ; 1672.29,3733.27 1736.48,3797.45 ; 1672.29,3733.27 1736.48,3797.45 ; v1@1759.95,5080.83 v1(1759.94,5082) v1@1759.94,5080.83 ; v1@1759.95,5080.83 v1@1778.95,5080.83 ; v1@1778.95,5080.83 1779.45,5080.83 v3@1779.45,5063.83 ; v1@1778.95,5080.83 v1(1778.95,5081.78) v1@1778.95,5080.83 ; v3@1779.45,5063.83 v3(1779.95,5063.83) 1780.2,5063.58 1797.7,5081.08 v1(1798.44,5082.36) ; v3@2155.68,4123.62 2158.31,4123.03 v3(2158.56,4122.5) 2158.17,4122.89 2157.39,4122.1 2154.17,4122.1 v3@2155.68,4123.62 ; 2208.95,4309.83 2286.52,4309.83 ; 436.31,1622.09 436.31,1626.09 447.18,1636.96 481.46,1636.96 493.83,1649.33 514.24,1649.33 514.74,1648.83 532.45,1648.83 548.63,1665 581.83,1665 646.78,1729.96 646.78,1764.62 646.31,1765.09 v1(646.31,1779.09) 676.31,1749.09 676.31,1728.23 567.17,1619.09 439.31,1619.09 436.31,1622.09 ; 1399.31,4370.34 1399.31,4404.09 1407.99,4404.09 1430.31,4381.77 1430.31,4370.13 1418.57,4358.39 v1(1418.57,4356.75) 1412.91,4356.75 1399.31,4370.34 ; 1743.31,4542.87 1752.1,4534.09 1779.7,4534.09 1787.69,4542.08 1787.69,4552.02 1770.31,4569.39 v1(1758.44,4569.39) 1752.62,4569.39 1743.31,4560.09 1743.31,4542.87 ; 2307.31,3175.04 2336.26,3146.09 2350.34,3146.09 2361.84,3157.59 2361.84,3188.69 v1(2344.93,3205.6) 2344.93,3206.75 2335.72,3206.75 2334.38,3208.09 2319.03,3208.09 2307.31,3196.37 2307.31,3175.04
  Inner Layer 2 w6: 1035.08,3855.11 1089.83,3855.11 v4(1092.97,3858.25) ; 1037.05,3811.13 1053.07,3811.13 1053.33,3811.39 1076.82,3811.39 v4(1077.22,3811) 1092.09,3811 1092.2,3811.11 v4(1107.08,3811.11) v4@1106.08,3812.11 ; v4@1077.22,3921.24 1080.09,3924.11 1099.08,3924.11 1114.08,3909.11 1114.08,3908.11
  Inner Layer 2 w8: v3(583.08,3885.11) 594.08,3885.37 v1(598.95,3885.49) ; v1(596.08,3819.11) 598.08,3821.11 v3(612.08,3821.11) ; v1(631.5,3999) 631.5,3982.33 631.5,3982.11 v3@631.82,3982.43 ; v3(636.08,3823.11) 649.91,3823.11 v1(651.18,3821.84) v1(651.18,3841.52) v1(651.18,3861.21) ; v3(648.08,3998.11) 651.18,3995 v1(651.18,3979.32) 650.08,3978.22 v3@650.08,3961.11 ; v3(648.08,4117.11) 651.19,4117.11 v1(670.87,4097.43) ; v3(648.32,3960.04) 648.95,3960.49 650.08,3960.49 v3@650.08,3961.11 ; v1(651.18,3900.58) v1(651.18,3920.26) v1(651.18,3939.95) 651.18,3960 v3@650.08,3961.11 ; v3(695.08,4080.11) 695.08,4077.74 v1(710.24,4077.74) ; v3(725.08,3803.11) 726.03,3802.15 v1(749.61,3802.15) 750.77,3803.32 v3@769.29,3803.32 ; v1(729.92,3743.1) v3(748.08,3743.11) ; v1(729.92,4136.8) 754.89,4136.8 v3(772.45,4119.25) 791.11,4119.25 v1(808.66,4136.8) 808.66,4135.5 828.35,4115.81 v1(828.35,4097.43) ; v1(749.61,3880.89) 750.82,3882.11 v3(793.08,3882.11) 793.58,3882.11 807.45,3882.11 v1(808.66,3880.89) v1@808.81,3880.75 ; v1(749.61,3959.63) v1(769.29,3939.95) 769.29,3921.11 v3(769.08,3920.11) ; v3(769.08,3803.11) v3@769.29,3803.32 ; v1(769.29,3821.84) v3@769.29,3803.32 ; v1(769.29,3999) v1(788.98,4018.69) v3@803.08,4018.69 ; v1(788.98,3743.1) v1@791.99,3746.11 ; v3@803.08,4018.11 v3(805.08,4016.11) ; v1@809.51,3822.68 816.08,3816.11 v3(823.08,3816.11) ; v1(854.08,3791.11) 863.08,3800.11 v3(867.08,3800.11) ; v3(893.15,4463.49) 893.15,4461.68 903.74,4451.09 904.1,4451.09 v1(909.08,4446.11) 909.08,4446.3 921.95,4446.3 v1(921.95,4446.49) ; v4(931.33,3085.71) 933.08,3085.71 933.08,3103.68 v3(936.9,3107.5) ; 1029.98,3826.74 1029.98,3818.2 ; v4(1029.98,3936.99) v4(1029.98,3952.73) ; v4@1056.95,3022.83 1056.95,3008.83 1053.95,3005.83 1053.95,2958.21 1064.39,2947.77 v1(1064.39,2913.67) ; v4@1061.59,4015.61 v4(1062,4015.02) ; v4(1092.97,3858.25) 1094.57,3859.85 1114.1,3840.33 v3(1114.1,3827.33) ; v4@1092.97,3889.74 1101.08,3889.74 1113.45,3902.11 1113.45,3907.47 1114.08,3908.11 ; v4@1106.08,3812.11 1106.08,3819.31 v3@1113.09,3826.32 ; v3(1106.25,3769.53) 1112.02,3763.76 v4(1124.46,3763.76) 1132.03,3763.76 1145.29,3750.49 ; v3(1112.08,3796.1) 1113.09,3796.1 v3@1113.09,3826.32 ; v3(1121.21,3856.64) 1124.95,3858.86 1140.21,3858.86 v4(1140.21,3858.25) ; v3(1186.95,3795.49) 1187.45,3795.49 v4(1187.46,3811) ; v3(1187.08,3764.1) v4(1187.46,3779.51) ; v4(1187.46,3952.73) v3(1203.08,3953.1) v4(1203.2,3936.99) ; 1225.53,3730.01 1234.82,3730.01 ; v3(1234.08,4020.1) 1246.06,4020.1 v4(1250.45,4015.73) ; v4@1250.45,3795.25 v3(1258.08,3811.1) v4(1266.2,3795.25) ; v4@1250.45,3889.74 v3(1256.08,3904.1) ; v4@1250.45,3921.24 v3(1256.08,3937.1) ; v1(1258,3608.8) 1263.95,3614.75 1263.95,3650.62 1266.19,3652.87 v4(1266.2,3685.02) ; v4(1297.69,3795.25) v4(1329.19,3795.25) ; v4(1297.69,3826.75) v4(1329.19,3826.75) ; v4(1329.19,3984.23) v3(1332.08,3968.1) ; v1(1739.95,3099.3) 1770.95,3099.3 1779.23,3107.58 1790.21,3107.58 v1(1790.21,3106.6) ; v3(1780.43,3418.88) 1812.72,3386.59 1824.65,3386.59 1826.72,3384.52 1830.58,3384.52 v1(1837.65,3391.59) ; v3(1785.65,3654.59) v1(1785.65,3670.59) ; v3(1792.65,3474.59) 1793.65,3475.59 v1(1815.65,3475.59) ; v1(1805.74,4050.69) 1806.2,4050.69 1806.2,4070.59 v3(1806.65,4070.59) ; v1(1825.65,3500.59) 1842.65,3483.59 v3(1845.65,3483.59) ; v1(1830.65,3670.28) 1830.65,3685.59 ; v3(1863.65,3803.59) v4(1863.66,3819.85) ; v3(1894.65,3804.59) 1894.9,3804.59 1894.9,3819.85 v4(1895.16,3819.85) ; v3(1896.65,3589.59) 1896.65,3580.6 v1(1909.33,3580.61) ; v1(1900.65,3425.59) 1900.15,3425.09 1911.15,3414.09 v3(1910.65,3413.59) ; v3(1910.65,3485.59) v1(1910.65,3500.75) ; v4(1910.9,3819.85) 1918.65,3812.1 v3(1918.65,3806.59) ; v1(1915.65,3540.59) v3(1915.65,3559.59) ; v1(1931.97,3580.61) 1932.14,3580.78 1942.49,3570.42 1943.49,3569.42 1942.93,3566.88 v3@1942.65,3565.59 ; v3(1975.65,3488.59) v1(1975.65,3504.27) ; v3(1994.65,3488.59) 1995,3488.59 1995,3504.27 v1(1995.34,3504.27) ; v1(2015.66,3570.49) v3@2015.66,3585.59 ; v3(2045.65,3442.59) 2045.81,3442.59 2045.81,3427.24 v1(2045.97,3427.24) ; v1(2046.65,4155.59) 2046.65,4153.09 v3(2061.65,4153.09) ; v3@2057.65,3372.59 v3@2057.99,3372.26 ; v3(2060.65,3455.59) 2061.91,3455.59 v1(2061.91,3470.62) ; v1(2060.65,3565.59) 2068.65,3573.59 v1(2106.65,3573.59) ; v3(2069.65,3427.59) 2069.65,3427.42 2085.34,3427.42 v1(2085.34,3427.24) ; v3(2073.65,3495.59) v1(2090.65,3495.59) 2090.65,3495.7 2112.37,3495.7 v3(2112.37,3495.81) ; v3(2074.65,3372.59) 2074.49,3372.76 2085.5,3383.77 v1(2085.34,3383.94) ; v3(2085.65,3455.59) v1(2085.65,3470.76) ; v3(2094.14,3620.67) 2094.9,3620.67 2094.9,3640.59 v1(2095.65,3640.59) ; v1(2110.5,3380.59) 2118.65,3380.59 2124.65,3386.59 v3(2122.65,3389.59) ; v1@2156.18,3458.14 v3@2167.64,3469.6 ; v1(2231.65,3760.59) 2233.06,3760.59 2233.06,3776.15 v3(2234.48,3776.15) ; v1(2281.24,3760.9) 2281.24,3762.25 v3@2311.65,3762.25 ; v1(2285.65,3425.59) v3(2297.65,3413.59) ; v1(2288.45,3653.03) 2288.55,3653.03 2288.55,3668.59 v3(2288.65,3668.59) ; v1(2295.65,3995.61) v3(2311.05,3995.61) ; v1(2296.27,3744.17) 2311.65,3759.56 v3@2311.65,3762.25 ; v3(2302.65,3929.59) 2302.65,3924.18 v1(2310.65,3916.18) 2320.65,3926.18 v3(2320.65,3928.59) ; v3@2306.65,3828.59 2307.22,3828.59 v3(2307.32,3828.49) ; v1(2310.65,3780.59) 2335.65,3805.59 v1(2335.65,3825.59) ; v3(2311.65,3763.59) v3@2311.65,3762.25 ; v1(2330.34,3870) 2330.34,3884.87 v3(2339.81,3894.34) ; v1@2332.65,3854.59 v1(2334.65,3854.59) ; v1(2350.37,3564.64) 2350.37,3564.22 2365.38,3564.22 v3(2365.38,3563.8) ; v1(2355.65,3915.59) 2370.65,3915.59 v3(2375.65,3910.59) ; v1(2531.71,3385.37) 2519.31,3397.77 2519.31,3483.39 v1(2538.18,3502.26) ; v3@631.82,3982.43 632.5,3983.11 v3(634.08,3983.11) v3@631.82,3982.43 ; 1029.98,3818.2 v4(1029.98,3811) 1030.11,3811.13 1037.05,3811.13 1029.98,3818.2 ; v3@1113.09,3826.32 v3(1114.1,3827.33) ; v3@1113.09,3826.32 1113.09,3827.33 v3(1114.1,3827.33)
  Inner Layer 2 w9: 1234.82,3730.01 1245.29,3730.01 1247.84,3732.57 1254.3,3732.57 ; v4(1249.04,3732.42) 1254.3,3732.57 ; v4(1282.48,3732.17) v4@1282.48,3736.55 ; v4(1297.69,3763.76) 1297.69,3751.76 v4@1282.48,3736.55 ; 1254.3,3732.57 1263.88,3732.84 1263.61,3732.57 ; 1254.3,3732.57 1263.61,3732.57 ; 1263.61,3732.57 1278.49,3732.57 1280.29,3734.37 v4@1282.48,3736.55
  Inner Layer 2 w10: v3(58.95,2953.49) 155.43,2953.49 180.35,2978.42 180.35,3070.82 144.33,3106.84 v1(140.53,3103.04) ; v4(1057.32,3227.44) 1057.13,3227.49 1057.13,3227.43 1073.05,3227.43 v4@1073.05,3227.21 ; 1177.33,3730.51 1206.84,3730.51 ; v4(1214.29,3730.78) v4@1210.8,3730.51 ; 1225.53,3730.01 1224.1,3730.01 1223.6,3730.51 v4@1210.8,3730.51 ; v1(1512.95,3255.11) v1(1512.95,3239.36) v1(1512.95,3223.62) v1(1512.95,3207.87) v1(1512.95,3192.12) 1512.95,3180.31 1517.21,3176.05 v1(1516.76,3175.59) ; v3@1763.19,3806.69 1763.52,3807.01 v3(1763.9,3807.37) 1773.9,3817.39 v1(1773.9,3828.76) ; v4(1863.66,3882.84) 1863.66,3893.48 ; 1206.51,3730.18 v4@1210.8,3730.51 ; 1206.51,3730.18 1203.9,3727.57 1204.73,3730.05 1206.51,3730.18 ; 1206.51,3730.18 1206.84,3730.51 ; 1206.84,3730.51 v4@1210.8,3730.51
  Inner Layer 2 w12: v1(55.95,911.49) 68.95,911.49 76.35,904.09 155.64,904.09 285.64,1034.09 671.55,1034.09 v1(689.95,1052.49) ; v3(58.95,2953.49) 58.95,2917.49 96.31,2880.13 96.31,2772.09 150.86,2717.54 150.86,2536.64 106.31,2492.09 v1(97.31,2492.09) ; v5(327.71,4640.53) 327.71,4644.09 430.95,4644.09 619.31,4832.45 v5(619.31,4855.09) ; v1(449.65,3935.9) 449.19,3936.36 460.75,3947.92 v3(489.82,3947.92) ; v1(449.84,3691.19) 449.84,3704.09 455.84,3710.09 v3(487.47,3710.09) ; v3(651.27,3727.69) 651.27,3742.72 671.1,3762.55 v1(670.87,3762.78) ; v1(712.31,1056.09) 747.31,1091.09 747.31,1108.25 747.31,1210.98 747.31,1253.45 747.31,1340.36 747.31,1392.43 747.31,1446.95 747.31,1658.71 711.94,1694.09 698.69,1694.09 674.95,1670.35 674.95,1539.85 674.95,1394.49 v1(722.95,1346.49) ; v1(746.95,2725.83) v3@770.21,2749.09 ; 770.21,2660.56 1847.75,2660.56 1907.21,2660.56 1907.95,2661.3 1942.72,2661.3 2149.48,2661.3 v5(2235.99,2747.81) ; v3(897.31,3300.09) 896.79,3300.61 907.48,3311.3 v1(906.95,3311.83) ; v4@1025.95,3180.45 v4@1041.56,3180.45 ; v3(1040.95,2895.83) 1042.35,2894.43 1046.07,2898.15 1052.53,2898.15 1063.31,2908.94 1063.31,2914.75 v1(1064.39,2913.67) ; v4(1041.57,3180.2) v4@1041.56,3180.45 ; v4(1057.32,3180.2) 1057.06,3180.45 1049.95,3180.45 ; v1(1069.31,3300.09) 1077.8,3291.6 1077.8,3275.65 v3(1077.37,3275.65) ; v4@1073.05,3227.21 1087.25,3227.21 1104.95,3244.91 1104.95,3246.83 ; 1093.95,3187.83 1086.95,3180.83 1050.33,3180.83 1049.95,3180.45 ; v1(1102.95,3338.83) 1126.95,3338.83 1126.95,3340.79 v3(1126.7,3340.79) ; v1(1126.95,3035.83) 1129.02,3033.76 v1(1129.02,2984.8) 1129.02,2982.77 v1(1136.62,2975.18) ; v1(1148.95,3063.83) 1148.95,3047.83 1158.97,3037.81 v3(1158.97,3034.65) 1161.95,3034.65 1161.95,3063.51 v1(1161.42,3063.51) ; v3(1254.31,3558.09) 1254.31,3605.11 v1(1258,3608.8) ; v3(1426.31,2990.09) 1430.31,2990.09 v1(1430.31,2958.09) ; v1(1739.95,3099.3) 1739.95,3108.14 v3@1752.03,3120.22 ; v1(1741.38,4149.63) 1741.38,4146.61 1762.65,4146.61 v3(1762.65,4143.59) ; v3(1750.73,3118.36) v3@1751.61,3117.86 ; v1(1856.31,4711.09) v3(1856.31,4726.09) v1(1856.31,4742.09) ; v1(2215.52,3958.42) 2214.36,3957.26 2224.73,3946.89 v3(2223.57,3945.73) ; v3@2271.65,3378.59 2271.65,3380.59 2287.65,3380.59 2295.06,3380.59 v1(2295.06,3385.59) ; v1(2350.65,3425.59) 2350.65,3425.51 2366.8,3425.51 v3(2366.8,3425.42) ; v3(2404.31,4220.09) 2404.31,4160.27 v1(2438.61,4125.97) ; v5@2518.25,4175.24 2518.25,4174.41 2533.65,4174.41 2533.65,4173.59 ; 2552.3,3345.49 v3(2619.95,3345.49) ; CON6401.8@2577.65,4175.59 2592.7,4175.59 CON6401.8@2593.05,4175.24 ; v4@1041.56,3180.45 1049.95,3180.45
  Inner Layer 2 w15: v3(1792.31,4633.09) v1(1792.31,4648.09) v1(1792.31,4660.09)
  Inner Layer 2 w20: v3(772.31,913.09) 781.31,904.09 ; 1093.95,3187.83 1136.95,3230.83 v1(1136.95,3239.83) ; 1104.95,3246.83 v1@1104.95,3334.09 ; 1655.31,798.09 1641.31,784.09 712.31,784.09 685.31,757.09 643.31,757.09 616.31,784.09 616.31,822.03 698.37,904.09 781.31,904.09 ; v3(2026.31,886.09) 1975.31,835.09 1379.81,835.09 1310.81,904.09 781.31,904.09
  Inner Layer 3 w4: v3(677.48,4382.29) 717.48,4422.28 v3(957.29,4422.28)
  Inner Layer 4 w3: 669.95,4119.25 669.1,4120.1 669.1,4150.63 678.95,4160.49 ; v3(1015.95,4126.49) 1015.95,4108.86 1022.81,4101.99 1022.81,4071.59 1034.31,4060.09 1069.31,4060.09 1078.31,4069.09 1085.41,4069.09 1097.31,4057.18 1097.31,4047.21 1095.31,4045.21 1095.31,4044.99 1085.34,4035.02 1080.78,4035.02 ; 1016.95,4053.49 1023.95,4046.49 1069.31,4046.49 1080.78,4035.02 ; 1080.66,4013.11 1080.78,4013.23 1080.78,4035.02 ; 1108.91,3543.33 1110.82,3545.24 1149.66,3545.24 1162.8,3558.37 1162.8,3605.37 ; 1121.69,3679.46 1130.93,3679.46 1147.05,3695.59 1162.2,3695.59 1171.3,3686.49 ; 1126.95,3736.53 1133.25,3736.53 1141.21,3744.49 1154.85,3744.49 1171.3,3728.03 1171.3,3686.49 ; 1135.3,3647.09 1135.8,3647.59 1154.89,3647.59 ; 1155.51,3598.09 1162.8,3605.37 ; 1154.89,3647.59 1164.95,3647.59 1171.3,3653.94 1171.3,3686.49 ; 1154.89,3647.59 1162.8,3639.68 1162.8,3605.37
